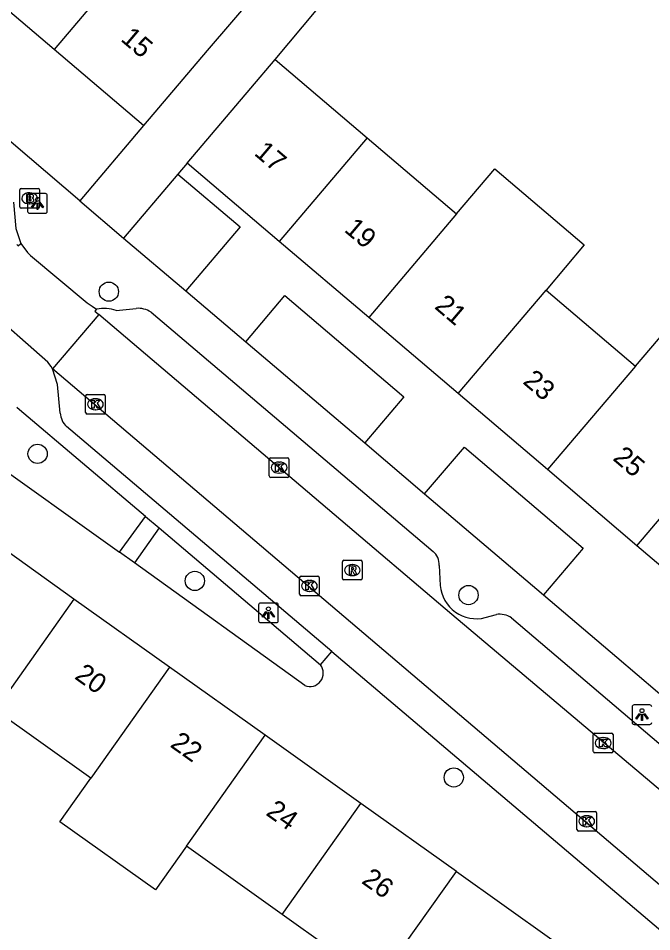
# Model space of a CAD drawing. Extents: x 162532 to 163264, y 381233 to 382042.
# Drawn here: x 163154.21 to 163186.43, y 381590.36 to 381636.8 of the extents above; entities that cross this region are included whole.
import ezdxf

# ---------------------------------------------------------------- set-up
doc = ezdxf.new("R2010")
doc.units = 0
for name, color, linetype in [('IMGEO_Boom', 7, 'Continuous'), ('IMGEO_Brandkraan', 7, 'Continuous'), ('IMGEO_Grasland_overig', 7, 'Continuous'), ('IMGEO_Groenvoorziening', 7, 'Continuous'), ('IMGEO_Kolk', 7, 'Continuous'), ('IMGEO_Lichtpunt', 7, 'Continuous'), ('IMGEO_Pand', 7, 'Continuous'), ('IMGEO_Pand_nummerreeks', 7, 'Continuous'), ('IMGEO_Rijbaan_lokaal_open', 7, 'Continuous'), ('IMGEO_Rioolput', 7, 'Continuous'), ('IMGEO_Voetpad_open', 7, 'Continuous')]:
    doc.layers.add(name, color=color, linetype=linetype)

msp = doc.modelspace()

# ---------------------------------------------------------------- linework, layer by layer
at = {"layer": 'IMGEO_Boom'}
for centre in [(163158.816, 381622.902), (163155.192, 381614.657), (163163.19, 381608.197), (163177.113, 381607.478), (163176.364, 381598.207)]:
    msp.add_circle(centre, 0.489, dxfattribs=at)
at = {"layer": 'IMGEO_Brandkraan'}
for p, q in [((163154.286, 381627.221), (163154.286, 381628.073)), ((163154.361, 381628.147), (163155.213, 381628.147)), ((163154.774, 381627.927), (163154.799, 381627.927)), ((163155.287, 381628.073), (163155.287, 381627.221)), ((163154.797, 381627.367), (163154.772, 381627.367)), ((163155.213, 381627.147), (163154.361, 381627.147))]:
    msp.add_line(p, q, dxfattribs=at)
for points in [[(163154.286, 381627.221), (163154.286, 381628.073)], [(163154.361, 381628.147), (163155.213, 381628.147)], [(163154.634, 381627.847), (163154.634, 381627.447), (163154.847, 381627.447)], [(163154.865, 381627.847), (163154.634, 381627.847)], [(163154.813, 381627.766), (163154.759, 381627.766), (163154.759, 381627.69)], [(163154.759, 381627.69), (163154.812, 381627.69)], [(163155.287, 381628.073), (163155.287, 381627.221)], [(163154.821, 381627.614), (163154.759, 381627.614), (163154.759, 381627.533)], [(163154.759, 381627.533), (163154.821, 381627.533)], [(163155.213, 381627.147), (163154.361, 381627.147)]]:
    msp.add_lwpolyline(points, dxfattribs=at)
for centre, radius, start, end in [((163154.363, 381628.071), 0.0765, 91.552, 178.448), ((163154.363, 381628.071), 0.0765, 91.552, 178.448), ((163154.814, 381627.728), 0.0379, 267.8285, 90.9355), ((163154.869, 381627.702), 0.145, 59.4692, 91.5367), ((163154.894, 381627.749), 0.0922, 285.5137, 58.1501), ((163155.211, 381628.071), 0.0765, 1.552, 88.448), ((163155.211, 381628.071), 0.0765, 1.552, 88.448), ((163154.822, 381627.573), 0.0404, 269.8759, 90.5077), ((163154.853, 381627.698), 0.251, 268.6676, 293.5347), ((163154.899, 381627.557), 0.105, 301.3115, 78.989), ((163154.363, 381627.223), 0.0765, 181.552, 268.448), ((163154.363, 381627.223), 0.0765, 181.552, 268.448), ((163155.211, 381627.223), 0.0765, 271.552, 358.448), ((163155.211, 381627.223), 0.0765, 271.552, 358.448)]:
    msp.add_arc(centre, radius, start, end, dxfattribs=at)
for centre, major_axis, ratio, start_param, end_param in [((163154.773, 381627.647), (-0.387, 0.002), 0.722429, 4.712389, 7.853982), ((163154.798, 381627.647), (-0.39, 0.002), 0.717154, 1.570796, 4.712389)]:
    msp.add_ellipse(centre, major_axis=major_axis, ratio=ratio, start_param=start_param, end_param=end_param, dxfattribs=at)
at = {"layer": 'IMGEO_Grasland_overig'}
msp.add_lwpolyline([(163162.328, 381628.874), (163165.493, 381626.194), (163162.731, 381622.942)], dxfattribs=at)
at = {"layer": 'IMGEO_Groenvoorziening'}
for points in [[(163165.78, 381620.352), (163167.777, 381622.704), (163173.818, 381617.55), (163171.832, 381615.212)], [(163174.881, 381612.622), (163176.901, 381615.001), (163182.949, 381609.858), (163180.931, 381607.482)]]:
    msp.add_lwpolyline(points, dxfattribs=at)
at = {"layer": 'IMGEO_Kolk'}
for p, q in [((163157.633, 381616.752), (163157.633, 381617.604)), ((163157.708, 381617.678), (163158.56, 381617.678)), ((163158.634, 381617.604), (163158.634, 381616.752)), ((163158.121, 381617.458), (163158.146, 381617.458)), ((163158.56, 381616.678), (163157.708, 381616.678)), ((163158.144, 381616.898), (163158.119, 381616.898)), ((163166.979, 381613.531), (163166.979, 381614.383)), ((163167.054, 381614.457), (163167.906, 381614.457)), ((163167.467, 381614.237), (163167.492, 381614.237)), ((163167.98, 381614.383), (163167.98, 381613.531)), ((163167.906, 381613.457), (163167.054, 381613.457)), ((163167.49, 381613.677), (163167.465, 381613.677)), ((163168.52, 381607.518), (163168.52, 381608.37)), ((163168.595, 381608.444), (163169.447, 381608.444)), ((163169.008, 381608.224), (163169.033, 381608.224)), ((163169.521, 381608.37), (163169.521, 381607.518)), ((163169.447, 381607.444), (163168.595, 381607.444)), ((163169.031, 381607.664), (163169.006, 381607.664)), ((163183.462, 381599.53), (163183.462, 381600.382)), ((163183.537, 381600.456), (163184.389, 381600.456)), ((163184.463, 381600.382), (163184.463, 381599.53)), ((163183.95, 381600.236), (163183.975, 381600.236)), ((163184.389, 381599.456), (163183.537, 381599.456)), ((163183.973, 381599.676), (163183.948, 381599.676)), ((163182.626, 381595.554), (163182.626, 381596.406)), ((163182.701, 381596.48), (163183.553, 381596.48)), ((163183.114, 381596.26), (163183.139, 381596.26)), ((163183.627, 381596.406), (163183.627, 381595.554)), ((163183.137, 381595.7), (163183.112, 381595.7)), ((163183.553, 381595.48), (163182.701, 381595.48))]:
    msp.add_line(p, q, dxfattribs=at)
for points in [[(163157.633, 381616.752), (163157.633, 381617.604)], [(163157.708, 381617.678), (163158.56, 381617.678)], [(163158.634, 381617.604), (163158.634, 381616.752)], [(163157.954, 381617.378), (163158.077, 381617.378), (163158.077, 381617.227), (163158.207, 381617.378), (163158.371, 381617.378), (163158.225, 381617.227), (163158.378, 381616.978), (163158.226, 381616.978), (163158.141, 381617.142), (163158.077, 381617.075), (163158.077, 381616.978), (163157.954, 381616.978), (163157.954, 381617.378)], [(163158.56, 381616.678), (163157.708, 381616.678)], [(163166.979, 381613.531), (163166.979, 381614.383)], [(163167.054, 381614.457), (163167.906, 381614.457)], [(163167.98, 381614.383), (163167.98, 381613.531)], [(163167.3, 381614.157), (163167.423, 381614.157), (163167.423, 381614.006), (163167.553, 381614.157), (163167.717, 381614.157), (163167.571, 381614.006), (163167.724, 381613.757), (163167.572, 381613.757), (163167.487, 381613.921), (163167.423, 381613.854), (163167.423, 381613.757), (163167.3, 381613.757), (163167.3, 381614.157)], [(163167.906, 381613.457), (163167.054, 381613.457)], [(163168.52, 381607.518), (163168.52, 381608.37)], [(163168.595, 381608.444), (163169.447, 381608.444)], [(163169.521, 381608.37), (163169.521, 381607.518)], [(163168.841, 381608.144), (163168.964, 381608.144), (163168.964, 381607.993), (163169.094, 381608.144), (163169.258, 381608.144), (163169.112, 381607.993), (163169.265, 381607.744), (163169.113, 381607.744), (163169.028, 381607.908), (163168.964, 381607.841), (163168.964, 381607.744), (163168.841, 381607.744), (163168.841, 381608.144)], [(163169.447, 381607.444), (163168.595, 381607.444)], [(163183.462, 381599.53), (163183.462, 381600.382)], [(163183.537, 381600.456), (163184.389, 381600.456)], [(163184.463, 381600.382), (163184.463, 381599.53)], [(163183.783, 381600.156), (163183.906, 381600.156), (163183.906, 381600.005), (163184.036, 381600.156), (163184.2, 381600.156), (163184.054, 381600.005), (163184.207, 381599.756), (163184.055, 381599.756), (163183.97, 381599.92), (163183.906, 381599.853), (163183.906, 381599.756), (163183.783, 381599.756), (163183.783, 381600.156)], [(163184.389, 381599.456), (163183.537, 381599.456)], [(163182.626, 381595.554), (163182.626, 381596.406)], [(163182.701, 381596.48), (163183.553, 381596.48)], [(163182.947, 381596.18), (163183.07, 381596.18), (163183.07, 381596.029), (163183.2, 381596.18), (163183.364, 381596.18), (163183.218, 381596.029), (163183.371, 381595.78), (163183.219, 381595.78), (163183.134, 381595.944), (163183.07, 381595.877), (163183.07, 381595.78), (163182.947, 381595.78), (163182.947, 381596.18)], [(163183.627, 381596.406), (163183.627, 381595.554)], [(163183.553, 381595.48), (163182.701, 381595.48)]]:
    msp.add_lwpolyline(points, dxfattribs=at)
for centre, start, end in [((163157.71, 381617.602), 91.552, 178.448), ((163157.71, 381617.602), 91.552, 178.448), ((163158.558, 381617.602), 1.552, 88.448), ((163158.558, 381617.602), 1.552, 88.448), ((163157.71, 381616.754), 181.552, 268.448), ((163157.71, 381616.754), 181.552, 268.448), ((163158.558, 381616.754), 271.552, 358.448), ((163158.558, 381616.754), 271.552, 358.448), ((163167.056, 381614.381), 91.552, 178.448), ((163167.056, 381614.381), 91.552, 178.448), ((163167.904, 381614.381), 1.552, 88.448), ((163167.904, 381614.381), 1.552, 88.448), ((163167.056, 381613.533), 181.552, 268.448), ((163167.056, 381613.533), 181.552, 268.448), ((163167.904, 381613.533), 271.552, 358.448), ((163167.904, 381613.533), 271.552, 358.448), ((163168.597, 381608.368), 91.552, 178.448), ((163168.597, 381608.368), 91.552, 178.448), ((163169.445, 381608.368), 1.552, 88.448), ((163169.445, 381608.368), 1.552, 88.448), ((163168.597, 381607.52), 181.552, 268.448), ((163168.597, 381607.52), 181.552, 268.448), ((163169.445, 381607.52), 271.552, 358.448), ((163169.445, 381607.52), 271.552, 358.448), ((163183.539, 381600.38), 91.552, 178.448), ((163183.539, 381600.38), 91.552, 178.448), ((163184.387, 381600.38), 1.552, 88.448), ((163184.387, 381600.38), 1.552, 88.448), ((163183.539, 381599.532), 181.552, 268.448), ((163183.539, 381599.532), 181.552, 268.448), ((163184.387, 381599.532), 271.552, 358.448), ((163184.387, 381599.532), 271.552, 358.448), ((163182.703, 381596.404), 91.552, 178.448), ((163182.703, 381596.404), 91.552, 178.448), ((163183.551, 381596.404), 1.552, 88.448), ((163183.551, 381596.404), 1.552, 88.448), ((163182.703, 381595.556), 181.552, 268.448), ((163182.703, 381595.556), 181.552, 268.448), ((163183.551, 381595.556), 271.552, 358.448), ((163183.551, 381595.556), 271.552, 358.448)]:
    msp.add_arc(centre, 0.0765, start, end, dxfattribs=at)
for centre, major_axis, ratio, start_param, end_param in [((163158.12, 381617.178), (-0.387, 0.002), 0.722429, 4.712389, 7.853982), ((163158.145, 381617.178), (-0.39, 0.002), 0.717154, 1.570796, 4.712389), ((163167.466, 381613.957), (-0.387, 0.002), 0.722429, 4.712389, 7.853982), ((163167.491, 381613.957), (-0.39, 0.002), 0.717154, 1.570796, 4.712389), ((163169.007, 381607.944), (-0.387, 0.002), 0.722429, 4.712389, 7.853982), ((163169.032, 381607.944), (-0.39, 0.002), 0.717154, 1.570796, 4.712389), ((163183.949, 381599.956), (-0.387, 0.002), 0.722429, 4.712389, 7.853982), ((163183.974, 381599.956), (-0.39, 0.002), 0.717154, 1.570796, 4.712389), ((163183.113, 381595.98), (-0.387, 0.002), 0.722429, 4.712389, 7.853982), ((163183.138, 381595.98), (-0.39, 0.002), 0.717154, 1.570796, 4.712389)]:
    msp.add_ellipse(centre, major_axis=major_axis, ratio=ratio, start_param=start_param, end_param=end_param, dxfattribs=at)
at = {"layer": 'IMGEO_Lichtpunt'}
for p, q in [((163154.687, 381627.792), (163154.687, 381626.985)), ((163154.687, 381627.792), (163154.687, 381626.985)), ((163155.589, 381627.887), (163154.781, 381627.887)), ((163155.589, 381627.887), (163154.781, 381627.887)), ((163155.683, 381626.985), (163155.683, 381627.792)), ((163155.683, 381626.985), (163155.683, 381627.792)), ((163154.781, 381626.891), (163155.589, 381626.891)), ((163154.781, 381626.891), (163155.589, 381626.891)), ((163166.436, 381606.977), (163166.436, 381606.17)), ((163166.436, 381606.977), (163166.436, 381606.17)), ((163167.338, 381607.072), (163166.53, 381607.072)), ((163167.338, 381607.072), (163166.53, 381607.072)), ((163167.432, 381606.17), (163167.432, 381606.977)), ((163167.432, 381606.17), (163167.432, 381606.977)), ((163166.53, 381606.076), (163167.338, 381606.076)), ((163166.53, 381606.076), (163167.338, 381606.076)), ((163185.437, 381601.801), (163185.437, 381600.994)), ((163185.437, 381601.801), (163185.437, 381600.994)), ((163186.339, 381601.896), (163185.531, 381601.896)), ((163186.339, 381601.896), (163185.531, 381601.896)), ((163185.531, 381600.9), (163186.339, 381600.9)), ((163185.531, 381600.9), (163186.339, 381600.9))]:
    msp.add_line(p, q, dxfattribs=at)
for points in [[(163155.061, 381627.456), (163155.1, 381627.428), (163154.912, 381627.166), (163154.874, 381627.193), (163155.061, 381627.456)], [(163155.163, 381627.408), (163155.21, 381627.408), (163155.21, 381627.086), (163155.163, 381627.086), (163155.163, 381627.408)], [(163155.273, 381627.428), (163155.311, 381627.455), (163155.498, 381627.193), (163155.459, 381627.165), (163155.273, 381627.428)], [(163166.81, 381606.641), (163166.849, 381606.613), (163166.661, 381606.351), (163166.623, 381606.378), (163166.81, 381606.641)], [(163166.912, 381606.593), (163166.959, 381606.593), (163166.959, 381606.271), (163166.912, 381606.271), (163166.912, 381606.593)], [(163167.022, 381606.613), (163167.06, 381606.64), (163167.247, 381606.378), (163167.208, 381606.35), (163167.022, 381606.613)], [(163185.811, 381601.465), (163185.85, 381601.437), (163185.662, 381601.175), (163185.624, 381601.202), (163185.811, 381601.465)], [(163185.913, 381601.417), (163185.96, 381601.417), (163185.96, 381601.095), (163185.913, 381601.095), (163185.913, 381601.417)], [(163186.023, 381601.437), (163186.061, 381601.464), (163186.248, 381601.202), (163186.209, 381601.174), (163186.023, 381601.437)]]:
    msp.add_lwpolyline(points, dxfattribs=at)
for centre in [(163155.186, 381627.59), (163166.935, 381606.775), (163185.936, 381601.599)]:
    msp.add_circle(centre, 0.0994, dxfattribs=at)
for centre, start, end in [((163154.781, 381627.792), 90, 180), ((163154.781, 381627.792), 90, 180), ((163155.589, 381627.792), 0, 90), ((163155.589, 381627.792), 0, 90), ((163154.781, 381626.985), 180, 270), ((163154.781, 381626.985), 180, 270), ((163155.589, 381626.985), 270, 0), ((163155.589, 381626.985), 270, 360), ((163166.53, 381606.977), 90, 180), ((163166.53, 381606.977), 90, 180), ((163167.338, 381606.977), 0, 90), ((163167.338, 381606.977), 0, 90), ((163166.53, 381606.17), 180, 270), ((163166.53, 381606.17), 180, 270), ((163167.338, 381606.17), 270, 0), ((163167.338, 381606.17), 270, 360), ((163185.531, 381601.801), 90, 180), ((163185.531, 381601.801), 90, 180), ((163186.339, 381601.801), 0, 90), ((163186.339, 381601.801), 0, 90), ((163185.531, 381600.994), 180, 270), ((163185.531, 381600.994), 180, 270), ((163186.339, 381600.994), 270, 0), ((163186.339, 381600.994), 270, 360)]:
    msp.add_arc(centre, 0.0946, start, end, dxfattribs=at)
at = {"layer": 'IMGEO_Pand'}
for points in [[(163162.834, 381643.222), (163162.699, 381643.063), (163160.503, 381640.476), (163156.035, 381635.214)], [(163167.545, 381639.532), (163167.39, 381639.348), (163165.057, 381636.604), (163163.826, 381635.156), (163160.588, 381631.345)], [(163156.035, 381635.214), (163151.486, 381639.08)], [(163160.588, 381631.345), (163156.035, 381635.214)], [(163162.803, 381629.433), (163166.042, 381633.243), (163167.279, 381634.698)], [(163167.279, 381634.698), (163171.959, 381630.718)], [(163171.959, 381630.718), (163167.487, 381625.452)], [(163171.959, 381630.718), (163176.507, 381626.851)], [(163167.487, 381625.452), (163162.803, 381629.433)], [(163176.507, 381626.851), (163178.456, 381629.146), (163183.004, 381625.278), (163181.055, 381622.983)], [(163176.507, 381626.851), (163172.036, 381621.586)], [(163172.036, 381621.586), (163167.487, 381625.452)], [(163176.585, 381617.719), (163181.055, 381622.983)], [(163181.055, 381622.983), (163185.603, 381619.116)], [(163176.585, 381617.719), (163172.036, 381621.586)], [(163185.603, 381619.116), (163187.551, 381621.41), (163191.674, 381617.903), (163190.151, 381615.248)], [(163185.603, 381619.116), (163181.133, 381613.853)], [(163181.133, 381613.853), (163176.585, 381617.719)], [(163185.682, 381609.986), (163190.151, 381615.248)], [(163185.682, 381609.986), (163181.133, 381613.853)], [(163157.042, 381607.274), (163152.178, 381610.736)], [(163190.231, 381606.12), (163185.682, 381609.986)], [(163157.042, 381607.274), (163153.034, 381601.633)], [(163161.905, 381603.811), (163157.042, 381607.274)], [(163161.905, 381603.811), (163157.898, 381598.17)], [(163166.769, 381600.348), (163161.905, 381603.811)], [(163157.898, 381598.17), (163153.034, 381601.633)], [(163162.762, 381594.707), (163166.769, 381600.348)], [(163171.632, 381596.886), (163166.769, 381600.348)], [(163162.762, 381594.707), (163161.191, 381592.495), (163156.327, 381595.958), (163157.898, 381598.17)], [(163167.625, 381591.245), (163171.632, 381596.886)], [(163176.495, 381593.423), (163171.632, 381596.886)], [(163167.625, 381591.245), (163162.762, 381594.707)], [(163172.488, 381587.782), (163176.495, 381593.423)], [(163176.495, 381593.423), (163181.358, 381589.961)], [(163172.488, 381587.782), (163167.625, 381591.245)]]:
    msp.add_lwpolyline(points, dxfattribs=at)
at = {"layer": 'IMGEO_Rijbaan_lokaal_open'}
for points in [[(163154.129, 381625.302), (163154.207, 381625.235), (163154.343, 381625.343)], [(163154.343, 381625.343), (163154.677, 381624.892), (163154.829, 381624.748), (163157.707, 381622.339), (163157.973, 381622.156), (163158.194, 381622.012)], [(163155.947, 381618.976), (163155.878, 381619.093), (163155.719, 381619.322), (163152.423, 381622.195), (163152.117, 381622.4), (163151.866, 381622.506)], [(163158.315, 381621.734), (163155.947, 381618.976)], [(163158.194, 381622.012), (163158.107, 381621.91), (163158.315, 381621.734)], [(163190.12, 381594.81), (163176.272, 381606.494), (163158.315, 381621.734)], [(163199.049, 381582.352), (163155.947, 381618.976)]]:
    msp.add_lwpolyline(points, dxfattribs=at)
at = {"layer": 'IMGEO_Rioolput'}
for p, q in [((163170.702, 381608.319), (163170.702, 381609.171)), ((163170.777, 381609.245), (163171.629, 381609.245)), ((163171.703, 381609.171), (163171.703, 381608.319)), ((163171.19, 381609.025), (163171.215, 381609.025)), ((163171.629, 381608.245), (163170.777, 381608.245)), ((163171.213, 381608.465), (163171.188, 381608.465))]:
    msp.add_line(p, q, dxfattribs=at)
for points in [[(163170.702, 381608.319), (163170.702, 381609.171)], [(163170.777, 381609.245), (163171.629, 381609.245)], [(163171.703, 381609.171), (163171.703, 381608.319)], [(163171.291, 381608.943), (163171.039, 381608.945), (163171.039, 381608.545)], [(163171.039, 381608.545), (163171.163, 381608.545), (163171.163, 381608.707), (163171.174, 381608.707)], [(163171.217, 381608.864), (163171.163, 381608.864), (163171.163, 381608.783)], [(163171.163, 381608.783), (163171.215, 381608.783)], [(163171.221, 381608.678), (163171.292, 381608.545), (163171.432, 381608.545), (163171.367, 381608.671)], [(163171.629, 381608.245), (163170.777, 381608.245)]]:
    msp.add_lwpolyline(points, dxfattribs=at)
for centre, radius, start, end in [((163170.779, 381609.169), 0.0765, 91.552, 178.448), ((163170.779, 381609.169), 0.0765, 91.552, 178.448), ((163171.627, 381609.169), 0.0765, 1.552, 88.448), ((163171.627, 381609.169), 0.0765, 1.552, 88.448), ((163171.173, 381608.654), 0.0533, 26.0293, 88.6989), ((163171.199, 381608.972), 0.19, 274.7715, 282.9687), ((163171.223, 381608.768), 0.0964, 77.0061, 93.1865), ((163171.237, 381608.825), 0.0378, 276.6634, 79.6772), ((163171.29, 381608.833), 0.109, 350.3612, 89.416), ((163171.288, 381608.833), 0.112, 277.5842, 350.9817), ((163171.272, 381608.618), 0.108, 29.5134, 73.7905), ((163170.779, 381608.321), 0.0765, 181.552, 268.448), ((163170.779, 381608.321), 0.0765, 181.552, 268.448), ((163171.627, 381608.321), 0.0765, 271.552, 358.448), ((163171.627, 381608.321), 0.0765, 271.552, 358.448)]:
    msp.add_arc(centre, radius, start, end, dxfattribs=at)
for centre, major_axis, ratio, start_param, end_param in [((163171.189, 381608.745), (-0.387, 0.002), 0.722429, 4.712389, 7.853982), ((163171.214, 381608.745), (-0.39, 0.002), 0.717154, 1.570796, 4.712389)]:
    msp.add_ellipse(centre, major_axis=major_axis, ratio=ratio, start_param=start_param, end_param=end_param, dxfattribs=at)
at = {"layer": 'IMGEO_Voetpad_open'}
for points in [[(163167.279, 381634.698), (163178.931, 381648.633), (163179.074, 381648.511), (163179.062, 381648.496)], [(163157.339, 381627.523), (163151.263, 381632.684)], [(163160.588, 381631.345), (163157.339, 381627.523)], [(163162.803, 381629.433), (163162.328, 381628.874)], [(163162.328, 381628.874), (163159.568, 381625.629)], [(163153.965, 381627.453), (163154.089, 381626.115), (163154.343, 381625.343)], [(163157.339, 381627.523), (163159.568, 381625.629)], [(163159.568, 381625.629), (163162.731, 381622.942)], [(163162.731, 381622.942), (163165.78, 381620.352)], [(163159.196, 381621.94), (163160.204, 381622.054)], [(163160.962, 381621.865), (163175.311, 381609.7)], [(163165.78, 381620.352), (163171.832, 381615.212)], [(163156.339, 381616.731), (163156.204, 381618.189), (163155.947, 381618.976)], [(163160.679, 381611.466), (163154.269, 381616.898), (163154.131, 381617.015)], [(163170.16, 381604.607), (163156.665, 381616.044)], [(163171.832, 381615.212), (163174.881, 381612.622)], [(163152.264, 381614.71), (163159.357, 381609.653)], [(163174.881, 381612.622), (163180.931, 381607.482)], [(163159.357, 381609.653), (163160.679, 381611.466)], [(163160.679, 381611.466), (163161.38, 381610.903)], [(163161.38, 381610.903), (163160.118, 381609.122)], [(163161.38, 381610.903), (163169.583, 381603.926)], [(163160.118, 381609.122), (163159.357, 381609.653)], [(163168.783, 381602.886), (163160.118, 381609.122)], [(163175.621, 381608.984), (163175.677, 381607.959)], [(163180.931, 381607.482), (163184.651, 381604.323), (163186.72, 381602.564), (163191.624, 381598.399)], [(163177.964, 381606.332), (163178.528, 381606.488)], [(163179.293, 381606.322), (163189.073, 381598.019)], [(163169.583, 381603.926), (163170.16, 381604.607)], [(163170.16, 381604.607), (163195.817, 381582.862)]]:
    msp.add_lwpolyline(points, dxfattribs=at)
for centre, radius, start, end in [((163158.565, 381620.165), 1.884, 70.4293, 101.3507), ((163160.294, 381620.802), 1.255, 57.8659, 94.1327), ((163157.409, 381616.818), 1.074, 184.6492, 226.122), ((163174.781, 381609.046), 0.842, 355.8016, 51.0198), ((163177.508, 381608.113), 1.838, 184.7921, 284.3509), ((163178.701, 381605.438), 1.064, 56.1675, 99.3465), ((163169.05, 381603.508), 0.677, 246.7272, 38.1357)]:
    msp.add_arc(centre, radius, start, end, dxfattribs=at)

# ---------------------------------------------------------------- texts
at = {"layer": 'IMGEO_Pand_nummerreeks'}
for s, rotation, p in [('15', 319.6409, (163159.373, 381635.685)), ('17', 319.6364, (163166.163, 381629.884)), ('19', 319.6364, (163170.741, 381625.993)), ('21', 319.6351, (163175.336, 381622.086)), ('23', 319.6364, (163179.829, 381618.268)), ('25', 319.6351, (163184.407, 381614.377)), ('20', 324.5501, (163157.024, 381603.26)), ('22', 324.5511, (163161.887, 381599.797)), ('24', 324.5501, (163166.756, 381596.331)), ('26', 324.5501, (163171.623, 381592.866))]:
    msp.add_text(s, height=1, rotation=rotation, dxfattribs=at).set_placement(p)

doc.saveas('drawing.dxf')
